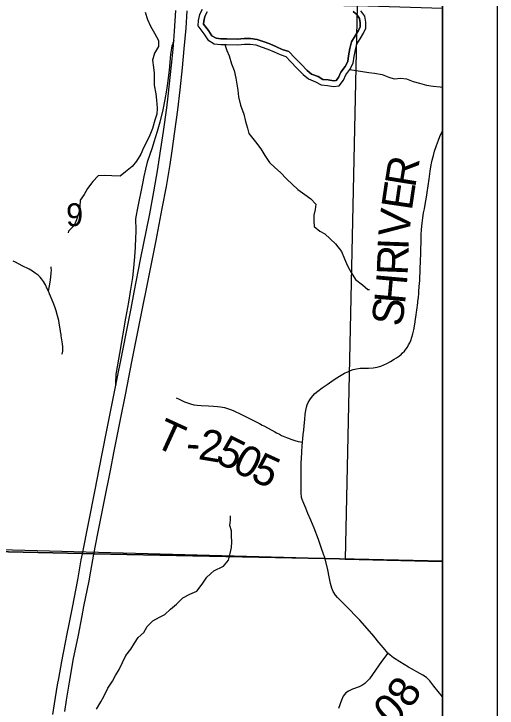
# Model space of a CAD drawing. Extents: x 0 to 34, y 0 to 22.
# Drawn here: x 29.531 to 30.417, y 18.296 to 19.567 of the extents above; entities that cross this region are included whole.
import ezdxf

# ---------------------------------------------------------------- set-up
doc = ezdxf.new("R2010")
doc.units = 0
for name, color, linetype in [('GM_X_Corporation', 7, 'Continuous'), ('GM_X_County_Road', 7, 'Continuous'), ('GM_X_County_Road_Text', 7, 'Continuous'), ('GM_X_Interchange_Ramps', 7, 'Continuous'), ('GM_X_Interstate_Route', 7, 'Continuous'), ('GM_X_Major_River', 7, 'Continuous'), ('GM_X_Minor_River', 7, 'Continuous'), ('GM_X_Section_Text', 7, 'Continuous'), ('GM_X_Township_Road', 7, 'Continuous'), ('GM_X_Township_Road_Text', 7, 'Continuous'), ('SH_Data', 7, 'Continuous')]:
    doc.layers.add(name, color=color, linetype=linetype)

msp = doc.modelspace()

# ---------------------------------------------------------------- linework, layer by layer
at = {"layer": 'GM_X_Corporation'}
for points in [[(26.6535, 14.621), (27.01, 14.6164), (27.046, 14.6155), (27.043, 14.755), (27.052, 15.403), (27.0676, 16.5549), (27.0694, 16.6556), (27.0775, 16.888), (27.0944, 18.0731), (27.1039, 18.5696), (27.1064, 18.6537), (27.3971, 18.6436), (28.3421, 18.6121), (28.7772, 18.6028), (29.0074, 18.5935), (29.6561, 18.5791), (29.6772, 18.5786), (30.101, 18.5701), (30.3167, 18.565), (30.3167, 20.9), (23.5167, 20.9)], [(26.3378, 16.673), (27.0694, 16.6556), (27.0775, 16.888), (27.0944, 18.0731), (27.1039, 18.5696), (27.1064, 18.6537), (27.3971, 18.6436), (28.3421, 18.6121), (28.7772, 18.6028), (29.0074, 18.5935), (29.6561, 18.5791), (29.6772, 18.5786), (30.101, 18.5701), (30.3167, 18.565), (30.3167, 20.9), (25.1014, 20.9)], [(23.5167, 14.1), (30.3167, 14.1), (30.3167, 18.565), (30.101, 18.5701), (29.6772, 18.5786), (29.6561, 18.5791), (29.0074, 18.5935), (28.7772, 18.6028), (28.3421, 18.6121), (27.3971, 18.6436), (27.1064, 18.6537), (27.1039, 18.5696), (27.0944, 18.0731), (27.0775, 16.888), (27.0694, 16.6556), (27.0676, 16.5549), (27.052, 15.403), (27.043, 14.755), (27.046, 14.6155), (27.01, 14.6164), (26.6535, 14.621)], [(30.3167, 14.5373), (30.3167, 18.565), (30.101, 18.5701), (29.6772, 18.5786), (29.6561, 18.5791), (29.0074, 18.5935), (28.7772, 18.6028), (28.3421, 18.6121), (27.3971, 18.6436), (27.1064, 18.6537), (27.1039, 18.5696), (27.0944, 18.0731)]]:
    msp.add_lwpolyline(points, dxfattribs=at)
for points in [[(30.1599, 19.5824), (30.1382, 18.5689), (29.1208, 18.5959), (29.1414, 19.6082)], [(30.3167, 18.5647), (30.3167, 19.5775), (30.1599, 19.5824), (30.1382, 18.5689)]]:
    msp.add_lwpolyline(points, close=True, dxfattribs=at)
at = {"layer": 'GM_X_County_Road'}
for points in [[(30.0599, 18.7827), (30.0606, 18.7889), (30.0614, 18.7969), (30.0622, 18.805), (30.0629, 18.813), (30.0639, 18.8248), (30.0648, 18.8341), (30.0659, 18.8408), (30.0673, 18.8469), (30.0687, 18.8516), (30.0705, 18.8556), (30.0731, 18.8605), (30.0763, 18.8651), (30.0787, 18.868), (30.0826, 18.872), (30.0878, 18.8764), (30.0958, 18.8823), (30.1049, 18.8888), (30.1178, 18.8975), (30.1277, 18.9039), (30.1368, 18.9092), (30.1441, 18.9127), (30.1481, 18.9143), (30.1529, 18.9158), (30.1589, 18.9173), (30.1656, 18.9183), (30.1718, 18.9187), (30.1811, 18.9188), (30.1895, 18.9194), (30.197, 18.9204), (30.2011, 18.9215), (30.2035, 18.9223), (30.2142, 18.9269), (30.2212, 18.9308), (30.2282, 18.9349), (30.2323, 18.9375), (30.2377, 18.9414), (30.2384, 18.942), (30.2405, 18.9438), (30.2428, 18.9458), (30.2466, 18.9498), (30.2497, 18.9537), (30.2522, 18.9573), (30.2545, 18.961), (30.2565, 18.9648), (30.2585, 18.9694), (30.2606, 18.9752), (30.2624, 18.9812), (30.2641, 18.989), (30.2659, 18.9994), (30.2672, 19.008), (30.2683, 19.016), (30.269, 19.0209), (30.2695, 19.0246), (30.2712, 19.0381), (30.2716, 19.0411), (30.2719, 19.0442), (30.2724, 19.0486), (30.2729, 19.0547), (30.2732, 19.0591), (30.2739, 19.0683), (30.2747, 19.0789), (30.2751, 19.0863), (30.2754, 19.0931), (30.2757, 19.0987), (30.2764, 19.1161), (30.2768, 19.1272), (30.277, 19.1359), (30.2773, 19.1501), (30.2777, 19.1625), (30.2782, 19.1723), (30.2791, 19.184), (30.2805, 19.1937), (30.282, 19.2028), (30.2833, 19.2101), (30.2849, 19.2185), (30.2871, 19.2319), (30.2885, 19.2404), (30.2918, 19.2648), (30.294, 19.2795), (30.296, 19.2911), (30.2978, 19.2996), (30.2998, 19.3081), (30.302, 19.3158), (30.3055, 19.3265), (30.3092, 19.3364), (30.3118, 19.3427), (30.3167, 19.3534)], [(30.1012, 18.5695), (30.1, 18.5734), (30.099, 18.5763), (30.0939, 18.5903), (30.0891, 18.6047), (30.081, 18.6255), (30.0781, 18.6328), (30.075, 18.6404), (30.0698, 18.6524), (30.0657, 18.6624), (30.0623, 18.6706), (30.0592, 18.6779), (30.0581, 18.6819), (30.0576, 18.6899), (30.0573, 18.6981), (30.0573, 18.7071), (30.0573, 18.7155), (30.0576, 18.7296), (30.0575, 18.7455), (30.0578, 18.7524), (30.0585, 18.7654), (30.0593, 18.7765), (30.0599, 18.7827)], [(30.3167, 18.3168), (30.3008, 18.3362), (30.2933, 18.3456), (30.2871, 18.3518), (30.2806, 18.3561), (30.2544, 18.371), (30.2385, 18.3805), (30.2268, 18.3882), (30.2208, 18.3929), (30.2163, 18.3967), (30.2084, 18.4063), (30.2, 18.416), (30.1905, 18.4277), (30.1785, 18.4416), (30.165, 18.4571), (30.1379, 18.4847), (30.1299, 18.4924), (30.1242, 18.4987), (30.1206, 18.5028), (30.1161, 18.5097), (30.1134, 18.5157), (30.111, 18.524), (30.1088, 18.5365), (30.1064, 18.5491), (30.1012, 18.5695)]]:
    msp.add_lwpolyline(points, dxfattribs=at)
at = {"layer": 'GM_X_Interchange_Ramps'}
msp.add_lwpolyline([(29.8238, 19.5187), (29.8223, 19.5141), (29.8214, 19.5112), (29.8206, 19.5085), (29.8197, 19.505), (29.819, 19.5005), (29.8182, 19.4936), (29.8155, 19.4646), (29.8126, 19.4405), (29.8108, 19.4276), (29.8078, 19.4105), (29.8038, 19.3916), (29.7981, 19.3693), (29.7933, 19.352), (29.7873, 19.3324), (29.7841, 19.3223), (29.7754, 19.2958), (29.7719, 19.2832), (29.769, 19.2699), (29.7664, 19.2565), (29.7574, 19.2114), (29.7542, 19.1955), (29.7538, 19.1912), (29.7537, 19.1869), (29.7542, 19.1763), (29.7542, 19.1676), (29.754, 19.1577), (29.7533, 19.1403), (29.7521, 19.1223), (29.7503, 19.1026), (29.7481, 19.0847), (29.7441, 19.0589), (29.7408, 19.0393), (29.7356, 19.0099), (29.7242, 18.9457), (29.7181, 18.9109), (29.7177, 18.9076), (29.7174, 18.9039), (29.7169, 18.8955), (29.7168, 18.894), (29.7169, 18.8917), (29.7172, 18.8896), (29.7178, 18.8877)], dxfattribs=at)
at = {"layer": 'GM_X_Interstate_Route'}
for points in [[(29.6563, 18.5785), (29.6676, 18.6342), (29.6797, 18.6958), (29.6873, 18.7336), (29.7, 18.7988), (29.7092, 18.8445), (29.714, 18.8691), (29.7178, 18.8877), (29.7297, 18.9481), (29.7382, 18.9913), (29.7455, 19.0279), (29.7514, 19.0577), (29.7632, 19.1174), (29.7798, 19.2015), (29.7873, 19.2418), (29.7945, 19.2835), (29.7991, 19.3123), (29.8049, 19.3523), (29.8109, 19.3954), (29.8135, 19.4169), (29.8197, 19.4738), (29.8225, 19.5029), (29.8238, 19.5187), (29.8251, 19.5357), (29.8278, 19.5735)], [(29.6774, 18.5781), (29.6848, 18.6156), (29.6971, 18.6765), (29.708, 18.7313), (29.7149, 18.7667), (29.7259, 18.8215), (29.7358, 18.8728), (29.7471, 18.9301), (29.7644, 19.0159), (29.7776, 19.0823), (29.7915, 19.1524), (29.8029, 19.2109), (29.8103, 19.2512), (29.8172, 19.2916), (29.8212, 19.3167), (29.8261, 19.3518), (29.8313, 19.3918), (29.8356, 19.4282), (29.84, 19.4689), (29.8432, 19.5035), (29.8464, 19.5413), (29.8485, 19.5729)], [(29.6024, 18.2842), (29.6053, 18.3036), (29.611, 18.3387), (29.6131, 18.3501), (29.6185, 18.3811), (29.6211, 18.3942), (29.6222, 18.3999), (29.6285, 18.4319), (29.6319, 18.4497), (29.638, 18.4802), (29.648, 18.5308), (29.6544, 18.5676), (29.6563, 18.5785)], [(29.6241, 18.2894), (29.6272, 18.3104), (29.6325, 18.3433), (29.6403, 18.3867), (29.6432, 18.4008), (29.649, 18.4294), (29.656, 18.4651), (29.6593, 18.482), (29.6686, 18.5289), (29.6721, 18.5466), (29.6774, 18.5781)]]:
    msp.add_lwpolyline(points, dxfattribs=at)
at = {"layer": 'GM_X_Major_River'}
for points in [[(29.8757, 19.5758), (29.8708, 19.5662), (29.8687, 19.5556), (29.868, 19.5454), (29.8791, 19.5311), (29.8864, 19.5198), (29.8981, 19.5127), (29.9099, 19.5113), (29.9208, 19.5114), (29.9412, 19.5105), (29.9533, 19.5118), (29.9639, 19.5119), (29.9741, 19.5105), (29.9844, 19.5072), (29.9965, 19.5028), (30.0079, 19.498), (30.0189, 19.4928), (30.0291, 19.4895), (30.0387, 19.4797), (30.0497, 19.4681), (30.0612, 19.4565), (30.0707, 19.4482), (30.084, 19.4431), (30.0939, 19.4375), (30.1056, 19.4361), (30.1169, 19.4347), (30.1271, 19.4359), (30.135, 19.4459), (30.1391, 19.4558), (30.1465, 19.4653), (30.1529, 19.4771), (30.1546, 19.4893), (30.1568, 19.5018), (30.1594, 19.512), (30.1653, 19.5216), (30.1717, 19.5319), (30.1761, 19.5414), (30.176, 19.552), (30.174, 19.563), (30.1671, 19.5731)], [(29.8849, 19.5711), (29.8807, 19.5628), (29.879, 19.5542), (29.8786, 19.5486), (29.8875, 19.5371), (29.8938, 19.5275), (29.9016, 19.5228), (29.9104, 19.5217), (29.921, 19.5218), (29.9409, 19.5209), (29.9527, 19.5222), (29.9646, 19.5223), (29.9765, 19.5206), (29.9877, 19.517), (30.0003, 19.5124), (30.0121, 19.5074), (30.0227, 19.5024), (30.0348, 19.4986), (30.0461, 19.4869), (30.0572, 19.4753), (30.0683, 19.464), (30.0761, 19.4572), (30.0884, 19.4525), (30.0971, 19.4475), (30.1068, 19.4464), (30.1169, 19.4451), (30.1216, 19.4457), (30.1259, 19.4512), (30.13, 19.461), (30.1378, 19.471), (30.1429, 19.4804), (30.1444, 19.4909), (30.1466, 19.5039), (30.1497, 19.5162), (30.1565, 19.5271), (30.1625, 19.5368), (30.1657, 19.5437), (30.1657, 19.551), (30.1642, 19.559), (30.1593, 19.5662), (30.1526, 19.572)], [(30.1526, 19.572), (30.1593, 19.5662), (30.1642, 19.559), (30.1657, 19.551), (30.1657, 19.5437), (30.1625, 19.5368), (30.1565, 19.5271), (30.1497, 19.5162), (30.1466, 19.5039), (30.1444, 19.4909), (30.1429, 19.4804), (30.1378, 19.471), (30.13, 19.461), (30.1259, 19.4512), (30.1216, 19.4457), (30.1169, 19.4451), (30.1068, 19.4464), (30.0971, 19.4475), (30.0884, 19.4525), (30.0761, 19.4572), (30.0683, 19.464), (30.0572, 19.4753), (30.0461, 19.4869), (30.0348, 19.4986), (30.0227, 19.5024), (30.0121, 19.5074), (30.0003, 19.5124), (29.9877, 19.517), (29.9765, 19.5206), (29.9646, 19.5223), (29.9527, 19.5222), (29.9409, 19.5209), (29.921, 19.5218), (29.9104, 19.5217), (29.9016, 19.5228), (29.8938, 19.5275), (29.8875, 19.5371), (29.8786, 19.5486), (29.879, 19.5542), (29.8807, 19.5628), (29.8849, 19.5711)]]:
    msp.add_lwpolyline(points, dxfattribs=at)
at = {"layer": 'GM_X_Minor_River'}
for points in [[(29.7717, 19.5709), (29.776, 19.5573), (29.781, 19.5452), (29.7883, 19.5324), (29.7956, 19.5185), (29.7957, 19.5075), (29.7883, 19.4957), (29.7846, 19.4824), (29.787, 19.4695), (29.7882, 19.4589), (29.7879, 19.4483), (29.7877, 19.4366), (29.7908, 19.4211), (29.7921, 19.4093), (29.7933, 19.3946), (29.7927, 19.3839), (29.789, 19.3725), (29.7846, 19.3577), (29.7801, 19.3452), (29.7738, 19.3326), (29.7686, 19.3219), (29.7634, 19.3105), (29.7556, 19.2979), (29.7474, 19.288), (29.7354, 19.278), (29.7256, 19.2703), (29.7101, 19.2706), (29.6965, 19.2716), (29.6855, 19.2711), (29.6754, 19.2607), (29.6657, 19.2474), (29.6594, 19.2367), (29.6523, 19.226), (29.6516, 19.2146), (29.6498, 19.2032), (29.6458, 19.1903), (29.6413, 19.1797), (29.6308, 19.1697), (29.6305, 19.1663)], [(29.9174, 19.5114), (29.9209, 19.5005), (29.9255, 19.4907), (29.9298, 19.4759), (29.9345, 19.4639), (29.9376, 19.4495), (29.9396, 19.4389), (29.9412, 19.4279), (29.9425, 19.4154), (29.946, 19.4003), (29.9526, 19.3837), (29.9553, 19.3701), (29.9588, 19.3584), (29.9616, 19.3486), (29.9738, 19.3332), (29.9834, 19.32), (29.9906, 19.308), (29.9991, 19.2952), (30.009, 19.2862), (30.0193, 19.2768), (30.0303, 19.2652), (30.0414, 19.2547), (30.0513, 19.2461), (30.0642, 19.2368), (30.0753, 19.2289), (30.0844, 19.2188), (30.083, 19.2093), (30.0808, 19.199), (30.0805, 19.1884), (30.0814, 19.1778), (30.0916, 19.1692), (30.1011, 19.1644), (30.1206, 19.146), (30.1313, 19.1321), (30.1371, 19.1186), (30.1421, 19.1057), (30.1494, 19.0937), (30.1571, 19.0809), (30.1696, 19.0712), (30.1799, 19.0629), (30.1825, 19.0626)], [(30.1465, 19.4653), (30.1814, 19.46), (30.192, 19.4586), (30.206, 19.4565), (30.2181, 19.4517), (30.228, 19.4487), (30.2404, 19.4496), (30.2506, 19.4482), (30.2628, 19.4434), (30.2741, 19.4405), (30.287, 19.4372), (30.2995, 19.4351), (30.312, 19.4337), (30.3167, 19.4332)], [(29.9241, 18.5669), (29.9271, 18.5788), (29.93, 18.5902), (29.9303, 18.6004), (29.9298, 18.6106), (29.9297, 18.6205), (29.9266, 18.6303), (29.9277, 18.6401), (29.928, 18.6481)], [(29.682, 18.2939), (29.6899, 18.3076), (29.6956, 18.317), (29.7028, 18.3322), (29.7116, 18.3454), (29.7173, 18.3553), (29.7237, 18.3667), (29.7298, 18.3795), (29.7362, 18.3924), (29.745, 18.4038), (29.7522, 18.4151), (29.7586, 18.425), (29.7692, 18.4344), (29.7753, 18.4454), (29.7855, 18.456), (29.7976, 18.4624), (29.8075, 18.4674), (29.8177, 18.4768), (29.8287, 18.4863), (29.8408, 18.498), (29.8533, 18.5048), (29.8662, 18.5101), (29.876, 18.523), (29.8848, 18.5355), (29.8976, 18.5472), (29.915, 18.556), (29.9241, 18.5669)]]:
    msp.add_lwpolyline(points, dxfattribs=at)
at = {"layer": 'GM_X_Township_Road'}
for points in [[(29.5942, 19.0598), (29.5921, 19.0641), (29.5887, 19.0712), (29.5851, 19.0774), (29.5816, 19.0823), (29.579, 19.0854), (29.5756, 19.0886), (29.5701, 19.0928), (29.565, 19.096), (29.5588, 19.0998), (29.5459, 19.1061), (29.5336, 19.1128), (29.5297, 19.1147)], [(29.5942, 19.0598), (29.5961, 19.0694), (29.5974, 19.0761), (29.5986, 19.0853), (29.5993, 19.0933), (29.5995, 19.0983), (29.5994, 19.102), (29.5992, 19.1039)], [(29.6188, 18.9444), (29.6198, 18.9466), (29.6201, 18.9476), (29.6206, 18.9493), (29.6208, 18.9516), (29.6208, 18.9547), (29.6204, 18.9578), (29.6197, 18.9632), (29.6186, 18.9704), (29.6175, 18.9778), (29.6172, 18.9802), (29.6165, 18.9857), (29.6163, 18.987), (29.6146, 18.9973), (29.613, 19.0059), (29.611, 19.0143), (29.6082, 19.0238), (29.6058, 19.0308), (29.6027, 19.0388), (29.5963, 19.0548), (29.5942, 19.0598)], [(29.828, 18.8644), (29.8337, 18.8619), (29.8438, 18.8571), (29.849, 18.8549), (29.8548, 18.853), (29.8609, 18.8516), (29.867, 18.8508), (29.8744, 18.8501), (29.8874, 18.8495), (29.8967, 18.8492), (29.9042, 18.8486), (29.9097, 18.8479), (29.917, 18.8464), (29.9224, 18.8449), (29.9276, 18.843), (29.9328, 18.8408), (29.9379, 18.8385), (29.9429, 18.8361), (29.9556, 18.8299), (29.9639, 18.8257), (29.97, 18.8226), (29.9749, 18.8201), (29.981, 18.8169), (29.9859, 18.8143), (29.9887, 18.8129), (29.9969, 18.8086), (30.0094, 18.8018), (30.0121, 18.8002), (30.0177, 18.7975), (30.0215, 18.7955), (30.0304, 18.7916), (30.0342, 18.7901), (30.0385, 18.7885), (30.0456, 18.7862), (30.0522, 18.7845), (30.0563, 18.7836), (30.0599, 18.7827)], [(30.2163, 18.3967), (30.2048, 18.3813), (30.1825, 18.3494), (30.1775, 18.344), (30.1739, 18.3411), (30.1688, 18.3375), (30.1636, 18.3347), (30.1518, 18.3303), (30.1442, 18.3268), (30.1394, 18.3238), (30.1346, 18.3177), (30.1311, 18.3103), (30.126, 18.2952)]]:
    msp.add_lwpolyline(points, dxfattribs=at)
at = {"layer": 'SH_Data'}
for points in [[(23.4167, 21), (30.4167, 21), (30.4167, 14), (23.4167, 14)], [(23.5167, 20.9), (30.3167, 20.9), (30.3167, 14.1), (23.5167, 14.1)]]:
    msp.add_lwpolyline(points, close=True, dxfattribs=at)

# ---------------------------------------------------------------- texts
at = {"layer": 'GM_X_County_Road_Text'}
for s, rotation, p in [('R', 80.7606, (30.2664, 19.2479)), ('E', 81.609, (30.2602, 19.206)), ('V', 84.0552, (30.2551, 19.1569)), ('I', 87.9135, (30.2543, 19.1346)), ('R', 87.8836, (30.2526, 19.088)), ('H', 84.7741, (30.2478, 19.0348)), ('S', 81.3239, (30.2416, 18.9932))]:
    msp.add_text(s, height=0.0568, rotation=rotation, dxfattribs=at).set_placement(p)
at = {"layer": 'GM_X_Section_Text'}
msp.add_text('9', height=0.0419, rotation=0, dxfattribs=at).set_placement((29.6265, 19.1786))
at = {"layer": 'GM_X_Township_Road_Text'}
for s, rotation, p in [('T', 335.3979, (29.785, 18.7767)), ('2', 350.4085, (29.8672, 18.7523)), ('5', 333.3023, (29.8975, 18.7478)), ('-', 356.3824, (29.8455, 18.7535)), ('0', 332.4086, (29.9286, 18.7322)), ('5', 335.3352, (29.9624, 18.7146)), ('8', 56.8456, (30.2578, 18.2931)), ('0', 43.9181, (30.2237, 18.2581))]:
    msp.add_text(s, height=0.0568, rotation=rotation, dxfattribs=at).set_placement(p)

doc.saveas('drawing.dxf')
